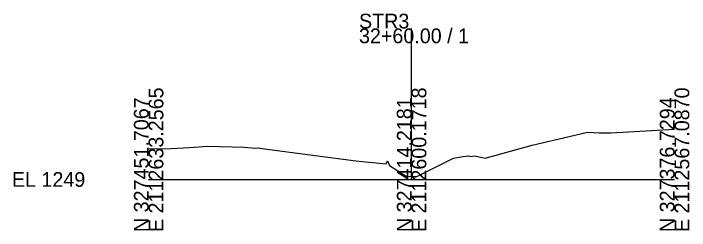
# Model space of a CAD drawing. Extents: x -26 to 103, y -10 to 14542.
# Drawn here: x -25.7 to 102.8, y 12990.3 to 13031.5 of the extents above; entities that cross this region are included whole.
import ezdxf

# ---------------------------------------------------------------- set-up
doc = ezdxf.new("R2010")
doc.units = 0
doc.layers.add('DESIGN - SHEET - Light Grid', color=7, linetype='Continuous')
doc.layers.add('SURVEY - GROUND - Top of Ground', color=7, linetype='Continuous')

msp = doc.modelspace()

# ---------------------------------------------------------------- linework, layer by layer
at = {"layer": 'DESIGN - SHEET - Light Grid'}
for p, q in [((50, 13000), (50, 13028.69)), ((0, 13000), (50, 13000)), ((50, 13000), (100, 13000))]:
    msp.add_line(p, q, dxfattribs=at)
at = {"layer": 'SURVEY - GROUND - Top of Ground'}
for p, q in [((79.97, 13008.15), (83.43, 13008.97)), ((83.43, 13008.97), (85.73, 13008.88)), ((85.73, 13008.88), (87.95, 13008.87)), ((87.95, 13008.87), (100, 13009.56)), ((72.94, 13006.49), (79.97, 13008.15)), ((7.74, 13006.1), (11.26, 13006.33)), ((11.26, 13006.33), (18.21, 13006.13)), ((64.02, 13004.06), (72.94, 13006.49)), ((0, 13005.83), (4.31, 13005.88)), ((4.31, 13005.88), (7.74, 13006.1)), ((18.21, 13006.13), (20.19, 13005.97)), ((20.19, 13005.97), (20.83, 13006.04)), ((20.83, 13006.04), (22.02, 13005.85)), ((22.02, 13005.85), (39.42, 13003.51)), ((51.01, 13000.55), (57.95, 13004.03)), ((57.95, 13004.03), (59.81, 13004.34)), ((59.81, 13004.34), (60.79, 13004.51)), ((60.79, 13004.51), (61.16, 13004.36)), ((61.16, 13004.36), (62.03, 13004.48)), ((62.03, 13004.48), (64.02, 13004.06)), ((39.42, 13003.51), (45.15, 13003)), ((45.15, 13003), (45.4, 13003.51)), ((45.4, 13003.51), (45.83, 13002.68)), ((45.83, 13002.68), (48.95, 13000.63)), ((48.95, 13000.63), (50, 13000.59)), ((50, 13000.59), (51.01, 13000.55))]:
    msp.add_line(p, q, dxfattribs=at)

# ---------------------------------------------------------------- texts
at = {"layer": 'DESIGN - SHEET - Light Grid'}
for s, p in [('STR3', (40, 13028.69)), ('32+60.00 / 1', (40, 13025.89)), ('EL 1249', (-26, 12998.6))]:
    msp.add_text(s, height=2.8, dxfattribs=at).set_placement(p)
for s, p in [('E 2112633.2565', (2.8, 12990)), ('E 2112600.1718', (52.8, 12990)), ('E 2112567.0870', (102.8, 12990)), ('N 327451.7067', (0, 12990)), ('N 327414.2181', (50, 12990)), ('N 327376.7294', (100, 12990))]:
    msp.add_text(s, height=2.8, rotation=90, dxfattribs=at).set_placement(p)

doc.saveas('drawing.dxf')
